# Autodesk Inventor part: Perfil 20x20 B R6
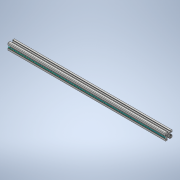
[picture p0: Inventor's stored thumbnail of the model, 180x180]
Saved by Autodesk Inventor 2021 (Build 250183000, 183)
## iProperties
Created: 2020-12
Part Number: Perfil 20x20 B R6
Material: Genérico
Document SubType Name: Modeling
Designer: ATOUZA
Density: 1 g/cm^3
Appearance: Valor por defecto
Author: ATOUZA
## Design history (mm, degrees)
sketch "Boceto1"
  geometry: L1 (4.5, 0.954)-(4.5, 3.232); L2 (4.646, 3.586)-(6.914, 5.854); L3 (7.268, 6)-(8, 6); L4 (8.5, 5.5)-(8.5, 3.6); L5 (9, 3.1)-(9.3, 3.1); L6 (9.5, 3.3)-(9.5, 3.65); L7 (9.5, 3.65)-(9.8, 3.65); L8 (10, 3.85)-(10, 8.5); L9 (8.5, 10)-(3.85, 10); L10 (3.65, 9.8)-(3.65, 9.5); L11 (3.65, 9.5)-(3.3, 9.5); L12 (3.1, 9.3)-(3.1, 9); L13 (3.6, 8.5)-(5.5, 8.5); L14 (6, 8)-(6, 7.268); L15 (5.854, 6.914)-(3.586, 4.646); L16 (3.232, 4.5)-(0.954, 4.5); L17 (0.854, 4.473)-(0.1, 4.038); L18 (-0.1, 4.038)-(-0.854, 4.473); L19 (-0.954, 4.5)-(-3.232, 4.5); L20 (-3.586, 4.646)-(-5.854, 6.914); L21 (-6, 7.268)-(-6, 8); L22 (-5.5, 8.5)-(-3.6, 8.5); L23 (-3.1, 9)-(-3.1, 9.3); L24 (-3.3, 9.5)-(-3.65, 9.5); L25 (-3.65, 9.5)-(-3.65, 9.8); L26 (-3.85, 10)-(-8.5, 10); L27 (-10, 8.5)-(-10, 3.85); L28 (-9.8, 3.65)-(-9.5, 3.65); L29 (-9.5, 3.65)-(-9.5, 3.3); L30 (-9.3, 3.1)-(-9, 3.1); L31 (-8.5, 3.6)-(-8.5, 5.5); L32 (-8, 6)-(-7.268, 6); L33 (-6.914, 5.854)-(-4.646, 3.586); L34 (-4.5, 3.232)-(-4.5, 0.954); L35 (-4.473, 0.854)-(-4.038, 0.1); L36 (-4.038, -0.1)-(-4.473, -0.854); L37 (-4.5, -0.954)-(-4.5, -3.232); L38 (-4.646, -3.586)-(-6.914, -5.854); L39 (-7.268, -6)-(-8, -6); L40 (-8.5, -5.5)-(-8.5, -3.6); L41 (-9, -3.1)-(-9.3, -3.1); L42 (-9.5, -3.3)-(-9.5, -3.65); L43 (-9.5, -3.65)-(-9.8, -3.65); L44 (-10, -3.85)-(-10, -8.5); L45 (-8.5, -10)-(-3.85, -10); L46 (-3.65, -9.8)-(-3.65, -9.5); L47 (-3.65, -9.5)-(-3.3, -9.5); L48 (-3.1, -9.3)-(-3.1, -9); L49 (-3.6, -8.5)-(-5.5, -8.5); L50 (-6, -8)-(-6, -7.268); L51 (-5.854, -6.914)-(-3.586, -4.646); L52 (-3.232, -4.5)-(-0.954, -4.5); L53 (1.258, -2.445)-(1.914, -2.99); L54 (2.992, -1.91)-(2.445, -1.258); L55 (2.445, 1.258)-(2.992, 1.91); L56 (1.914, 2.99)-(1.258, 2.445); L57 (-1.258, 2.445)-(-1.914, 2.99); L58 (-2.992, 1.91)-(-2.445, 1.258); L59 (-2.445, -1.258)-(-2.992, -1.91); L60 (-1.914, -2.99)-(-1.258, -2.445); L61 (1.258, -2.445)-(1.914, -2.99); L62 (2.992, -1.91)-(2.445, -1.258); L63 (2.445, 1.258)-(2.992, 1.91); L64 (1.914, 2.99)-(1.258, 2.445)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; A1 r 0.5 centre (5, 3.232) between (4.646, 3.586) and (4.5, 3.232); A2 r 0.5 centre (7.268, 5.5) between (7.268, 6) and (6.914, 5.854); A3 r 0.5 centre (8, 5.5) between (8.5, 5.5) and (8, 6); A4 r 0.5 centre (9, 3.6) between (8.5, 3.6) and (9, 3.1); A5 r 0.2 centre (9.3, 3.3) between (9.3, 3.1) and (9.5, 3.3); A6 r 0.2 centre (9.8, 3.85) between (9.8, 3.65) and (10, 3.85); A7 r 1.5 centre (8.5, 8.5) between (10, 8.5) and (8.5, 10); A8 r 0.2 centre (3.85, 9.8) between (3.85, 10) and (3.65, 9.8); A9 r 0.2 centre (3.3, 9.3) between (3.3, 9.5) and (3.1, 9.3); A10 r 0.5 centre (3.6, 9) between (3.1, 9) and (3.6, 8.5); A11 r 0.5 centre (5.5, 8) between (6, 8) and (5.5, 8.5); A12 r 0.5 centre (5.5, 7.268) between (5.854, 6.914) and (6, 7.268); A13 r 0.5 centre (3.232, 5) between (3.232, 4.5) and (3.586, 4.646); A14 r 0.2 centre (0.954, 4.3) between (0.954, 4.5) and (0.854, 4.473); A15 r 0.2 centre (0, 4.211) between (-0.1, 4.038) and (0.1, 4.038); A16 r 0.2 centre (-0.954, 4.3) between (-0.854, 4.473) and (-0.954, 4.5); A17 r 0.5 centre (-3.232, 5) between (-3.586, 4.646) and (-3.232, 4.5); A18 r 0.5 centre (-5.5, 7.268) between (-6, 7.268) and (-5.854, 6.914); A19 r 0.5 centre (-5.5, 8) between (-5.5, 8.5) and (-6, 8); A20 r 0.5 centre (-3.6, 9) between (-3.6, 8.5) and (-3.1, 9); A21 r 0.2 centre (-3.3, 9.3) between (-3.1, 9.3) and (-3.3, 9.5); A22 r 0.2 centre (-3.85, 9.8) between (-3.65, 9.8) and (-3.85, 10); A23 r 1.5 centre (-8.5, 8.5) between (-8.5, 10) and (-10, 8.5); A24 r 0.2 centre (-9.8, 3.85) between (-10, 3.85) and (-9.8, 3.65); A25 r 0.2 centre (-9.3, 3.3) between (-9.5, 3.3) and (-9.3, 3.1); A26 r 0.5 centre (-9, 3.6) between (-9, 3.1) and (-8.5, 3.6); A27 r 0.5 centre (-8, 5.5) between (-8, 6) and (-8.5, 5.5); A28 r 0.5 centre (-7.268, 5.5) between (-6.914, 5.854) and (-7.268, 6); A29 r 0.5 centre (-5, 3.232) between (-4.5, 3.232) and (-4.646, 3.586); A30 r 0.2 centre (-4.3, 0.954) between (-4.5, 0.954) and (-4.473, 0.854); A31 r 0.2 centre (-4.211, 0) between (-4.038, -0.1) and (-4.038, 0.1); A32 r 0.2 centre (-4.3, -0.954) between (-4.473, -0.854) and (-4.5, -0.954); A33 r 0.5 centre (-5, -3.232) between (-4.646, -3.586) and (-4.5, -3.232); A34 r 0.5 centre (-7.268, -5.5) between (-7.268, -6) and (-6.914, -5.854); A35 r 0.5 centre (-8, -5.5) between (-8.5, -5.5) and (-8, -6); A36 r 0.5 centre (-9, -3.6) between (-8.5, -3.6) and (-9, -3.1); A37 r 0.2 centre (-9.3, -3.3) between (-9.3, -3.1) and (-9.5, -3.3); A38 r 0.2 centre (-9.8, -3.85) between (-9.8, -3.65) and (-10, -3.85); A39 r 1.5 centre (-8.5, -8.5) between (-10, -8.5) and (-8.5, -10); A40 r 0.2 centre (-3.85, -9.8) between (-3.85, -10) and (-3.65, -9.8); A41 r 0.2 centre (-3.3, -9.3) between (-3.3, -9.5) and (-3.1, -9.3); A42 r 0.5 centre (-3.6, -9) between (-3.1, -9) and (-3.6, -8.5); A43 r 0.5 centre (-5.5, -8) between (-6, -8) and (-5.5, -8.5); A44 r 0.5 centre (-5.5, -7.268) between (-5.854, -6.914) and (-6, -7.268); A45 r 0.5 centre (-3.232, -5) between (-3.232, -4.5) and (-3.586, -4.646); A46 r 2.75 centre (0, 0) between (-1.258, -2.445) and (1.258, -2.445); A47 r 3.55 centre (0, 0) between (1.914, -2.99) and (2.992, -1.91); A48 r 2.75 centre (0, 0) between (2.445, -1.258) and (2.445, 1.258); A49 r 3.55 centre (0, 0) between (2.992, 1.91) and (1.914, 2.99); A50 r 2.75 centre (0, 0) between (1.258, 2.445) and (-1.258, 2.445); A51 r 3.55 centre (0, 0) between (-1.914, 2.99) and (-2.992, 1.91); A52 r 2.75 centre (0, 0) between (-2.445, 1.258) and (-2.445, -1.258); A53 r 3.55 centre (0, 0) between (-2.992, -1.91) and (-1.914, -2.99); A54 r 2.75 centre (0, 0) between (-1.258, -2.445) and (1.258, -2.445); A55 r 3.55 centre (0, 0) between (1.914, -2.99) and (2.992, -1.91); A56 r 2.75 centre (0, 0) between (2.445, -1.258) and (2.445, 1.258); A57 r 3.55 centre (0, 0) between (2.992, 1.91) and (1.914, 2.99); A58 r 2.75 centre (0, 0) between (1.258, 2.445) and (-1.258, 2.445); A59 r 3.55 centre (0, 0) between (-1.914, 2.99) and (-2.992, 1.91); A60 r 2.75 centre (0, 0) between (-2.445, 1.258) and (-2.445, -1.258); A61 r 3.55 centre (0, 0) between (-2.992, -1.91) and (-1.914, -2.99); A62 r 0.5 centre (-8, -5.5) between (-8.5, -5.5) and (-8, -6); A63 r 0.2 centre (-4.211, 0) between (-4.038, -0.1) and (-4.038, 0.1); A64 r 0.5 centre (-7.268, 5.5) between (-6.914, 5.854) and (-7.268, 6)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; 1 further point
  constraints: 324 end point, 198 point on circle, 99 centre point, 2 point on line, 6 other
extrude "Extrusión1" new body sketch "Boceto1" distance "d0" = 450; taper "d1" = 0 deg
sketch "Boceto3"
  geometry: L1 (0, -3.85)-(450, -3.95); L2 (0, -3.95)-(450, -3.95) reference
  constraints: 2 end point, 1 parallel
node "Sólido1"
